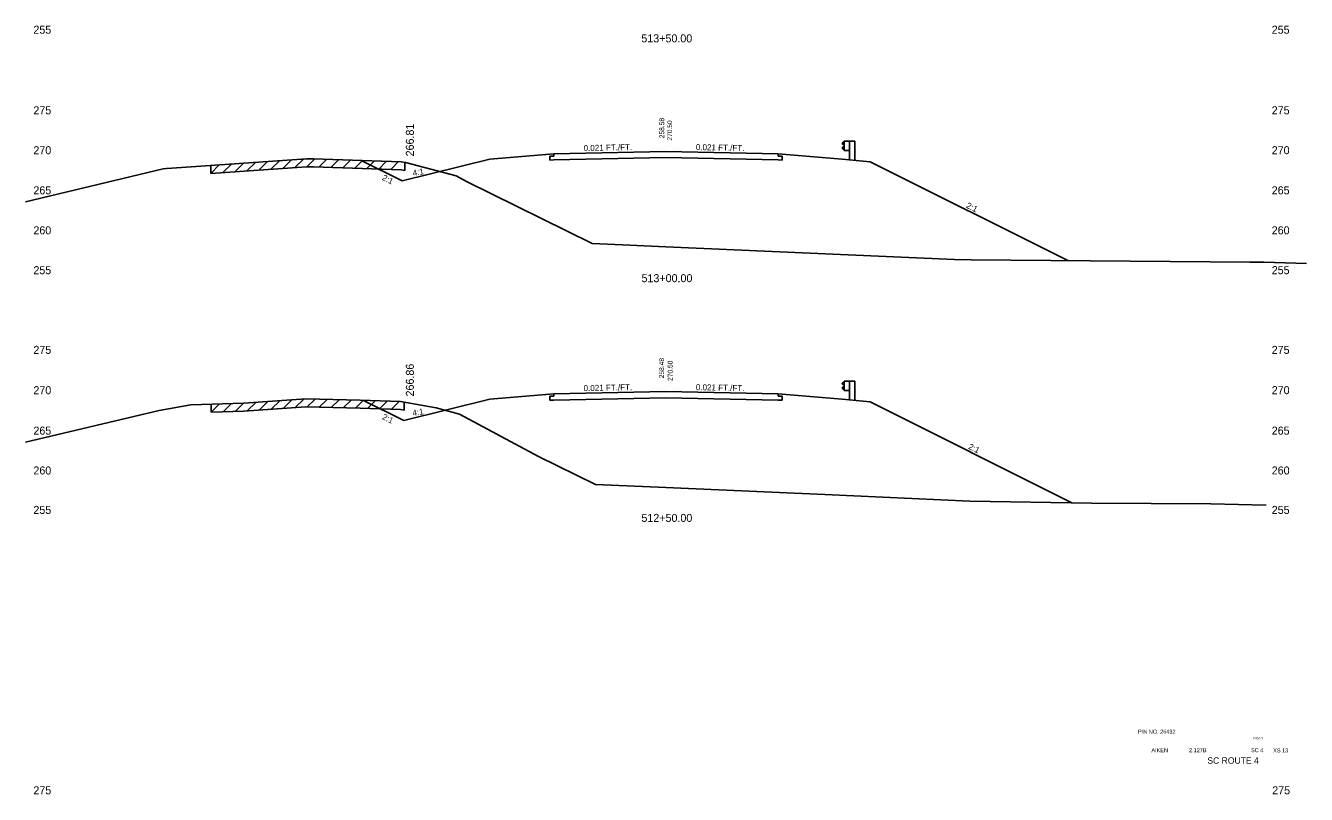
# Model space of a CAD drawing. Extents: x 883 to 1160, y 1002 to 4323.
# Drawn here: x 1000 to 1160, y 2475.1 to 2571.2 of the extents above; entities that cross this region are included whole.
import ezdxf

# ---------------------------------------------------------------- set-up
doc = ezdxf.new("R2010")
doc.units = 0
for name, color, linetype in [('Level 1', 7, 'Continuous'), ('Level 10', 7, 'Continuous'), ('Level 11', 7, 'Continuous'), ('Level 12', 7, 'Continuous'), ('Level 24', 7, 'Continuous'), ('Level 3', 7, 'Continuous'), ('Level 32', 7, 'Continuous'), ('Level 33', 7, 'Continuous'), ('Level 59', 7, 'Continuous'), ('Level 6', 7, 'Continuous'), ('Level 60', 7, 'Continuous'), ('Level 61', 7, 'Continuous'), ('Level 7', 7, 'Continuous')]:
    doc.layers.add(name, color=color, linetype=linetype)

msp = doc.modelspace()

# ---------------------------------------------------------------- linework, layer by layer
at = {"layer": 'Level 11'}
for p, q in [((1066, 2555.21), (1066, 2554.91)), ((1094, 2554.91), (1094, 2555.21)), ((1066, 2554.91), (1065.5, 2554.9)), ((1065.5, 2554.9), (1065.5, 2554.42)), ((1065.5, 2554.42), (1066, 2554.43)), ((1094.5, 2554.9), (1094, 2554.91)), ((1094, 2554.43), (1094.5, 2554.42)), ((1094.5, 2554.42), (1094.5, 2554.9)), ((1066, 2524.91), (1065.5, 2524.9)), ((1065.5, 2524.9), (1065.5, 2524.42)), ((1066, 2525.21), (1066, 2524.91)), ((1094, 2524.91), (1094, 2525.21)), ((1094.5, 2524.9), (1094, 2524.91)), ((1094.5, 2524.42), (1094.5, 2524.9)), ((1065.5, 2524.42), (1066, 2524.43)), ((1094, 2524.43), (1094.5, 2524.42))]:
    msp.add_line(p, q, dxfattribs=at)
at = {"layer": 'Level 12'}
for p, q in [((1080, 2554.72), (1066, 2554.43)), ((1094, 2554.43), (1080, 2554.72)), ((1080, 2524.72), (1066, 2524.43)), ((1094, 2524.43), (1080, 2524.72))]:
    msp.add_line(p, q, dxfattribs=at)
at = {"layer": 'Level 24'}
for p, q in [((1102.27, 2556.72), (1102, 2556.52)), ((1102, 2556.52), (1102, 2556.47)), ((1102, 2556.47), (1102.27, 2556.27)), ((1102, 2555.95), (1102.27, 2556.15)), ((1102, 2555.9), (1102, 2555.95)), ((1102.27, 2555.7), (1102, 2555.9)), ((1102.27, 2555.63), (1102.27, 2556.79)), ((1102.27, 2556.79), (1102.94, 2556.79)), ((1102.27, 2555.63), (1102.94, 2555.63)), ((1102.94, 2556.79), (1102.94, 2554.45)), ((1102.94, 2556.79), (1103.6, 2556.79)), ((1103.6, 2556.79), (1103.6, 2554.38)), ((1102.27, 2526.72), (1102, 2526.52)), ((1102, 2526.52), (1102, 2526.47)), ((1102, 2526.47), (1102.27, 2526.27)), ((1102.27, 2525.63), (1102.27, 2526.79)), ((1102.27, 2526.79), (1102.94, 2526.79)), ((1102.94, 2526.79), (1102.94, 2524.45)), ((1102.94, 2526.79), (1103.6, 2526.79)), ((1103.6, 2526.79), (1103.6, 2524.38)), ((1102, 2525.95), (1102.27, 2526.15)), ((1102, 2525.9), (1102, 2525.95)), ((1102.27, 2525.7), (1102, 2525.9)), ((1102.27, 2525.63), (1102.94, 2525.63))]:
    msp.add_line(p, q, dxfattribs=at)
at = {"layer": 'Level 59'}
for p, q in [((1066, 2555.21), (1080, 2555.5)), ((1080, 2555.5), (1094, 2555.21)), ((1066, 2525.21), (1080, 2525.5)), ((1080, 2525.5), (1094, 2525.21))]:
    msp.add_line(p, q, dxfattribs=at)
at = {"layer": 'Level 6'}
for p, q in [((1058, 2554.54), (1066, 2555.21)), ((1094, 2555.21), (1102, 2554.54)), ((1102, 2554.54), (1105.5, 2554.19)), ((1058, 2524.54), (1066, 2525.21)), ((1094, 2525.21), (1102, 2524.54)), ((1102, 2524.54), (1105.5, 2524.19))]:
    msp.add_line(p, q, dxfattribs=at)
at = {"layer": 'Level 60'}
for p, q in [((1018.28, 2553.4), (1035.1, 2554.58)), ((1035.1, 2554.58), (1035.95, 2554.56)), ((1035.95, 2554.56), (1046.9, 2554.21)), ((1046.9, 2554.21), (1047.47, 2554.11)), ((1047.47, 2554.11), (1053.79, 2552.44)), ((1000, 2549.22), (1017.2, 2553.31)), ((1017.2, 2553.31), (1017.61, 2553.38)), ((1017.61, 2553.38), (1018.28, 2553.4)), ((1053.79, 2552.44), (1055.06, 2551.76)), ((1055.06, 2551.76), (1070.79, 2543.99)), ((1070.79, 2543.99), (1074.55, 2543.83)), ((1074.55, 2543.83), (1080, 2543.58)), ((1080, 2543.58), (1116.04, 2541.98)), ((1116.04, 2541.98), (1118.13, 2541.95)), ((1118.13, 2541.95), (1152.92, 2541.67)), ((1152.92, 2541.67), (1154.67, 2541.64)), ((1154.67, 2541.64), (1160, 2541.49)), ((1016.67, 2523.12), (1020.66, 2523.84)), ((1020.66, 2523.84), (1027.26, 2524.04)), ((1027.26, 2524.04), (1035.02, 2524.58)), ((1035.02, 2524.58), (1041.8, 2524.4)), ((1041.8, 2524.4), (1046.84, 2524.24)), ((1046.84, 2524.24), (1051.3, 2523.44)), ((1051.3, 2523.44), (1054.2, 2522.68)), ((1000, 2519.15), (1016.67, 2523.12)), ((1054.2, 2522.68), (1064.08, 2517.38)), ((1064.08, 2517.38), (1071.19, 2513.87)), ((1071.19, 2513.87), (1080, 2513.48)), ((1080, 2513.48), (1099.85, 2512.61)), ((1099.85, 2512.61), (1117.96, 2511.81)), ((1117.96, 2511.81), (1133.16, 2511.56)), ((1133.16, 2511.56), (1148.05, 2511.44)), ((1148.05, 2511.44), (1154.96, 2511.3))]:
    msp.add_line(p, q, dxfattribs=at)
at = {"layer": 'Level 61'}
for p, q in [((1024.2, 2553.82), (1023.13, 2552.74)), ((1023.13, 2553.74), (1023.13, 2552.74)), ((1025.7, 2553.92), (1024.63, 2552.85)), ((1027.2, 2554.03), (1026.13, 2552.95)), ((1028.7, 2554.13), (1027.63, 2553.06)), ((1030.2, 2554.24), (1029.13, 2553.16)), ((1031.7, 2554.34), (1030.63, 2553.27)), ((1033.2, 2554.45), (1032.13, 2553.37)), ((1034.7, 2554.55), (1033.63, 2553.48)), ((1036.1, 2554.55), (1035.13, 2553.58)), ((1037.6, 2554.51), (1036.63, 2553.54)), ((1039.1, 2554.46), (1038.13, 2553.49)), ((1040.6, 2554.41), (1039.63, 2553.44)), ((1042.1, 2554.36), (1041.13, 2553.39)), ((1043.6, 2554.32), (1042.63, 2553.35)), ((1045.1, 2554.27), (1044.13, 2553.3)), ((1046.6, 2554.22), (1045.63, 2553.25)), ((1047.36, 2553.13), (1047.36, 2554.13)), ((1023.13, 2552.74), (1035.1, 2553.58)), ((1035.1, 2553.58), (1035.95, 2553.56)), ((1035.95, 2553.56), (1046.9, 2553.21)), ((1046.9, 2553.21), (1047.36, 2553.13)), ((1024.22, 2523.95), (1023.19, 2522.91)), ((1023.19, 2523.91), (1023.19, 2522.91)), ((1025.72, 2523.99), (1024.69, 2522.96)), ((1027.22, 2524.04), (1026.19, 2523)), ((1027.26, 2523.04), (1035.02, 2523.58)), ((1028.77, 2524.14), (1027.69, 2523.07)), ((1030.27, 2524.25), (1029.19, 2523.17)), ((1031.77, 2524.35), (1030.69, 2523.28)), ((1033.27, 2524.46), (1032.19, 2523.38)), ((1034.77, 2524.56), (1033.69, 2523.49)), ((1035.02, 2523.58), (1041.8, 2523.4)), ((1036.17, 2524.55), (1035.19, 2523.58)), ((1037.67, 2524.51), (1036.69, 2523.53)), ((1039.17, 2524.47), (1038.19, 2523.49)), ((1040.67, 2524.43), (1039.69, 2523.45)), ((1042.16, 2524.39), (1041.19, 2523.41)), ((1041.8, 2523.4), (1046.84, 2523.24)), ((1043.66, 2524.34), (1042.69, 2523.37)), ((1045.16, 2524.29), (1044.19, 2523.32)), ((1046.66, 2524.24), (1045.69, 2523.27)), ((1046.84, 2523.24), (1047.29, 2523.16)), ((1047.29, 2523.16), (1047.29, 2524.16)), ((1023.19, 2522.91), (1027.26, 2523.04))]:
    msp.add_line(p, q, dxfattribs=at)
at = {"layer": 'Level 7'}
for p, q in [((1041.93, 2554.37), (1047.05, 2551.81)), ((1058, 2554.54), (1047.05, 2551.81)), ((1105.5, 2554.19), (1130.18, 2541.85)), ((1042.2, 2524.38), (1047.25, 2521.86)), ((1058, 2524.54), (1047.25, 2521.86)), ((1105.5, 2524.19), (1130.68, 2511.6))]:
    msp.add_line(p, q, dxfattribs=at)

# ---------------------------------------------------------------- texts
at = {"layer": 'Level 1'}
for s, height, p in [('513+50.00', 1, (1076.92, 2569.13)), ('513+00.00', 1, (1076.94, 2539.16)), ('512+50.00', 1, (1076.93, 2509.2)), ('PIN NO. 26432', 0.5, (1138.97, 2482.74)), ('AIKEN', 0.5, (1140.64, 2480.42)), (' 2.127B', 0.5, (1145.15, 2480.42)), ('SC 4', 0.5, (1153.09, 2480.42)), ('XS 13', 0.5, (1155.85, 2480.39)), ('SC ROUTE 4', 0.8, (1147.63, 2478.98))]:
    msp.add_text(s, height=height, dxfattribs=at).set_placement(p)
at = {"layer": 'Level 10'}
for s, p in [('258.58', (1079.78, 2557.15)), ('258.48', (1079.75, 2527.15))]:
    msp.add_text(s, height=0.6, rotation=90, dxfattribs=at).set_placement(p)
at = {"layer": 'Level 3'}
for s, height, p in [(' 255', 1, (1000.6, 2570.21)), (' 255', 1, (1155.3, 2570.21)), (' 275', 1, (1000.6, 2560.14)), (' 275', 1, (1155.3, 2560.14)), (' 270', 1, (1000.6, 2555.15)), (' 270', 1, (1155.3, 2555.15)), (' 265', 1, (1000.6, 2550.14)), (' 265', 1, (1155.3, 2550.14)), (' 260', 1, (1000.6, 2545.14)), (' 260', 1, (1155.3, 2545.14)), (' 255', 1, (1000.6, 2540.16)), (' 255', 1, (1155.3, 2540.16)), (' 275', 1, (1000.6, 2530.2)), (' 275', 1, (1155.3, 2530.2)), (' 270', 1, (1000.6, 2525.16)), (' 270', 1, (1155.3, 2525.16)), (' 265', 1, (1000.6, 2520.11)), (' 265', 1, (1155.3, 2520.11)), (' 260', 1, (1000.6, 2515.13)), (' 260', 1, (1155.3, 2515.13)), (' 255', 1, (1000.6, 2510.2)), (' 255', 1, (1155.3, 2510.2)), ('ROAD', 0.3, (1153.38, 2482.01)), (' 275', 1, (1000.6, 2475.16)), (' 275', 1, (1155.36, 2475.16))]:
    msp.add_text(s, height=height, dxfattribs=at).set_placement(p)
at = {"layer": 'Level 32'}
for s, rotation, p in [('0.021 FT./FT.', 1.1916, (1069.71, 2555.54)), ('0.021 FT./FT.', 358.8084, (1083.72, 2555.67)), ('2:1', 333.435, (1044.46, 2551.98)), ('4:1', 9.4623, (1048.42, 2552.43)), ('2:1', 333.435, (1117.44, 2548.5)), ('0.021 FT./FT.', 1.1916, (1069.71, 2525.54)), ('0.021 FT./FT.', 358.8084, (1083.72, 2525.67)), ('4:1', 9.4623, (1048.39, 2522.43)), ('2:1', 333.435, (1044.47, 2522.08)), ('2:1', 333.435, (1117.7, 2518.37))]:
    msp.add_text(s, height=0.75, rotation=rotation, dxfattribs=at).set_placement(p)
at = {"layer": 'Level 33'}
for s, p in [('266.81', (1048.5, 2554.88)), ('266.86', (1048.5, 2524.88))]:
    msp.add_text(s, height=1, rotation=90, dxfattribs=at).set_placement(p)
at = {"layer": 'Level 59'}
for p in [(1080.76, 2556.62), (1080.82, 2526.59)]:
    msp.add_text(' 270.50', height=0.6, rotation=90, dxfattribs=at).set_placement(p)

doc.saveas('drawing.dxf')
